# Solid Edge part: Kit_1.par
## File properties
Sűrűség: 0,000 kg/m^3
Pontosság: 0,990
Author: ahadarics
Last saved by: ahadarics
Revision: 76
Username: ahadarics
Dokumentum tartalom típus: 0
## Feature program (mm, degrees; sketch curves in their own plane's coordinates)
base feature "unnamed BaseFeature 1"
thread "unnamed Thread 1"
chamfer "unnamed Chamfer 1"
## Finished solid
Body 1: solid body, 27 faces, 30 edges, 5 vertices, 1 internal void.
  Faces by surface: cylinder 10, plane 9, cone 8
  Edges by curve: circle 24, line 5, intersection 1
Bounding box of the edges (mm): 30.000 x 39.500 x 28.500, from (-15.0872, -80.2138, -14.9118) to (14.9128, -40.7138, 13.5882).
Cylindrical faces by radius (mm): R1 x1, R5 x1, R6.995 x1, R7 x2, R9.85 x1, R11 x2, R13.5 x1, R15 x1
Conical faces (half-angle, radius in mm at the cone's reference point): 45 deg R1.1 x1, 45 deg R5.25 x2, 45 deg R6.75 x2, 45 deg R7.15 x1, 45 deg R9.5 x1, 60 deg R10.425 x1
Planar faces by outward normal: +y 2, +z 1, -y 6
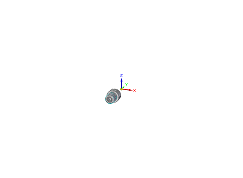
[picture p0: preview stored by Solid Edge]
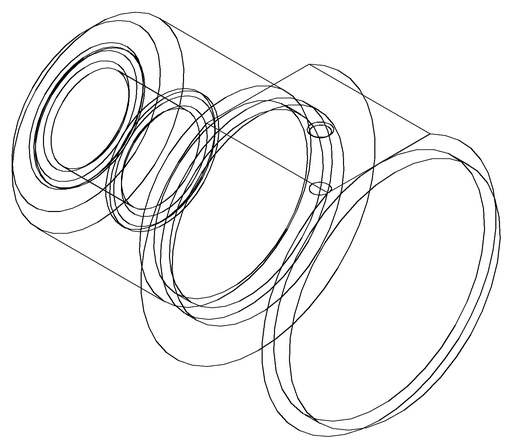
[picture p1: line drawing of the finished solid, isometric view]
